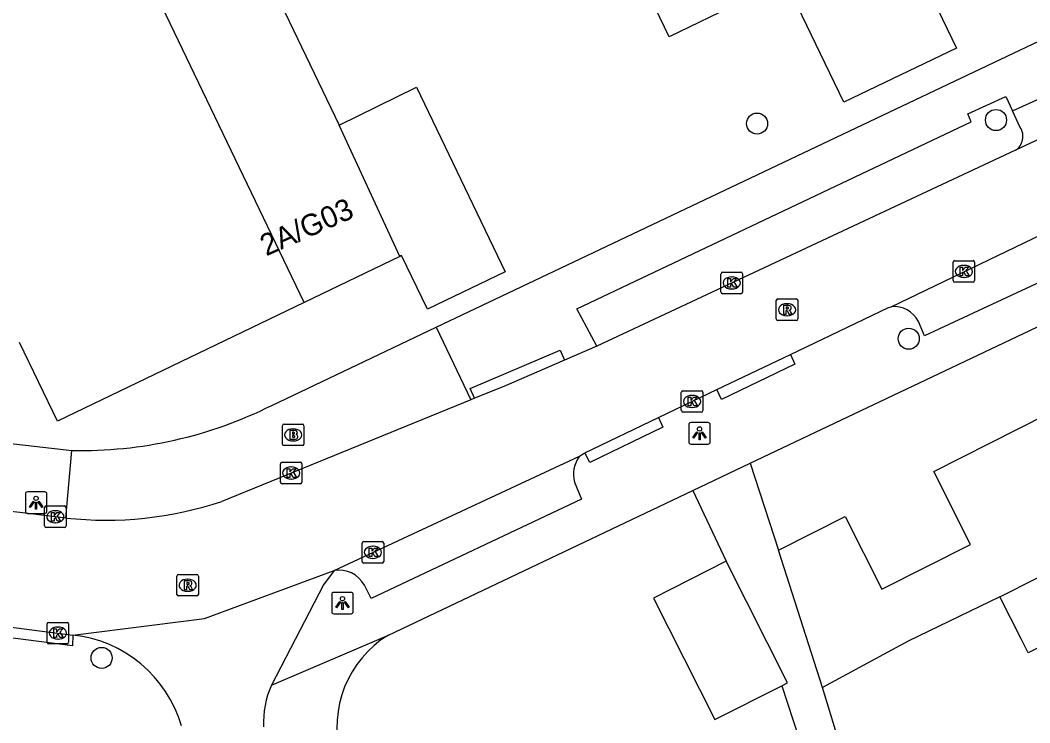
# Model space of a CAD drawing. Extents: x 162250 to 162654, y 380744 to 381605.
# Drawn here: x 162422.34 to 162469.23, y 381351.06 to 381383.66 of the extents above; entities that cross this region are included whole.
import ezdxf

# ---------------------------------------------------------------- set-up
doc = ezdxf.new("R2010")
doc.units = 0
for name, color, linetype in [('IMGEO_Boom', 7, 'Continuous'), ('IMGEO_Brandkraan', 7, 'Continuous'), ('IMGEO_Kolk', 7, 'Continuous'), ('IMGEO_Lichtpunt', 7, 'Continuous'), ('IMGEO_Pand', 7, 'Continuous'), ('IMGEO_Pand_nummerreeks', 7, 'Continuous'), ('IMGEO_Parkeervlak_open', 7, 'Continuous'), ('IMGEO_Rijbaan_lokaal_open', 7, 'Continuous'), ('IMGEO_Rioolput', 7, 'Continuous'), ('IMGEO_Voetpad_open', 7, 'Continuous')]:
    doc.layers.add(name, color=color, linetype=linetype)

msp = doc.modelspace()

# ---------------------------------------------------------------- linework, layer by layer
at = {"layer": 'IMGEO_Boom'}
for centre in [(162456.565, 381378.859), (162467.661, 381379.024), (162463.607, 381368.877), (162426.124, 381354.067)]:
    msp.add_circle(centre, 0.489, dxfattribs=at)
at = {"layer": 'IMGEO_Brandkraan'}
for p, q in [((162434.521, 381363.989), (162434.521, 381364.841)), ((162434.596, 381364.915), (162435.448, 381364.915)), ((162435.522, 381364.841), (162435.522, 381363.989)), ((162435.009, 381364.695), (162435.034, 381364.695)), ((162435.448, 381363.915), (162434.596, 381363.915)), ((162435.032, 381364.135), (162435.007, 381364.135))]:
    msp.add_line(p, q, dxfattribs=at)
for points in [[(162434.521, 381363.989), (162434.521, 381364.841)], [(162434.596, 381364.915), (162435.448, 381364.915)], [(162435.522, 381364.841), (162435.522, 381363.989)], [(162434.869, 381364.615), (162434.869, 381364.215), (162435.082, 381364.215)], [(162435.1, 381364.615), (162434.869, 381364.615)], [(162435.048, 381364.534), (162434.994, 381364.534), (162434.994, 381364.458)], [(162434.994, 381364.458), (162435.047, 381364.458)], [(162435.056, 381364.382), (162434.994, 381364.382), (162434.994, 381364.301)], [(162435.448, 381363.915), (162434.596, 381363.915)], [(162434.994, 381364.301), (162435.056, 381364.301)]]:
    msp.add_lwpolyline(points, dxfattribs=at)
for centre, radius, start, end in [((162434.598, 381364.839), 0.0765, 91.552, 178.448), ((162434.598, 381364.839), 0.0765, 91.552, 178.448), ((162435.446, 381364.839), 0.0765, 1.552, 88.448), ((162435.446, 381364.839), 0.0765, 1.552, 88.448), ((162435.049, 381364.496), 0.0379, 267.8285, 90.9355), ((162435.057, 381364.341), 0.0404, 269.8759, 90.5077), ((162435.104, 381364.47), 0.145, 59.4692, 91.5367), ((162435.129, 381364.517), 0.0922, 285.5137, 58.1501), ((162435.134, 381364.325), 0.105, 301.3115, 78.989), ((162434.598, 381363.991), 0.0765, 181.552, 268.448), ((162434.598, 381363.991), 0.0765, 181.552, 268.448), ((162435.088, 381364.466), 0.251, 268.6676, 293.5347), ((162435.446, 381363.991), 0.0765, 271.552, 358.448), ((162435.446, 381363.991), 0.0765, 271.552, 358.448)]:
    msp.add_arc(centre, radius, start, end, dxfattribs=at)
for centre, major_axis, ratio, start_param, end_param in [((162435.008, 381364.415), (-0.387, 0.002), 0.722429, 4.712389, 7.853982), ((162435.033, 381364.415), (-0.39, 0.002), 0.717154, 1.570796, 4.712389)]:
    msp.add_ellipse(centre, major_axis=major_axis, ratio=ratio, start_param=start_param, end_param=end_param, dxfattribs=at)
at = {"layer": 'IMGEO_Kolk'}
for p, q in [((162465.668, 381371.572), (162465.668, 381372.424)), ((162465.743, 381372.498), (162466.595, 381372.498)), ((162466.669, 381372.424), (162466.669, 381371.572)), ((162454.889, 381371.04), (162454.889, 381371.892)), ((162454.964, 381371.966), (162455.816, 381371.966)), ((162455.89, 381371.892), (162455.89, 381371.04)), ((162466.156, 381372.278), (162466.181, 381372.278)), ((162455.377, 381371.746), (162455.402, 381371.746)), ((162466.595, 381371.498), (162465.743, 381371.498)), ((162466.179, 381371.718), (162466.154, 381371.718)), ((162455.816, 381370.966), (162454.964, 381370.966)), ((162455.4, 381371.186), (162455.375, 381371.186)), ((162453.047, 381365.539), (162453.047, 381366.391)), ((162453.122, 381366.465), (162453.974, 381366.465)), ((162453.535, 381366.245), (162453.56, 381366.245)), ((162454.048, 381366.391), (162454.048, 381365.539)), ((162453.974, 381365.465), (162453.122, 381365.465)), ((162453.558, 381365.685), (162453.533, 381365.685)), ((162434.427, 381362.219), (162434.427, 381363.071)), ((162434.502, 381363.145), (162435.354, 381363.145)), ((162435.428, 381363.071), (162435.428, 381362.219)), ((162434.915, 381362.925), (162434.94, 381362.925)), ((162435.354, 381362.145), (162434.502, 381362.145)), ((162434.938, 381362.365), (162434.913, 381362.365)), ((162423.55, 381361.117), (162424.402, 381361.117)), ((162423.475, 381360.191), (162423.475, 381361.043)), ((162423.963, 381360.897), (162423.988, 381360.897)), ((162424.476, 381361.043), (162424.476, 381360.191)), ((162423.986, 381360.337), (162423.961, 381360.337)), ((162424.402, 381360.117), (162423.55, 381360.117)), ((162438.223, 381358.54), (162438.223, 381359.392)), ((162438.298, 381359.466), (162439.15, 381359.466)), ((162438.711, 381359.246), (162438.736, 381359.246)), ((162439.224, 381359.392), (162439.224, 381358.54)), ((162439.15, 381358.466), (162438.298, 381358.466)), ((162438.734, 381358.686), (162438.709, 381358.686)), ((162423.592, 381354.79), (162423.592, 381355.642)), ((162423.667, 381355.716), (162424.519, 381355.716)), ((162424.08, 381355.496), (162424.105, 381355.496)), ((162424.593, 381355.642), (162424.593, 381354.79)), ((162424.519, 381354.716), (162423.667, 381354.716)), ((162424.103, 381354.936), (162424.078, 381354.936))]:
    msp.add_line(p, q, dxfattribs=at)
for points in [[(162465.668, 381371.572), (162465.668, 381372.424)], [(162465.743, 381372.498), (162466.595, 381372.498)], [(162466.669, 381372.424), (162466.669, 381371.572)], [(162454.889, 381371.04), (162454.889, 381371.892)], [(162454.964, 381371.966), (162455.816, 381371.966)], [(162455.89, 381371.892), (162455.89, 381371.04)], [(162465.989, 381372.198), (162466.112, 381372.198), (162466.112, 381372.047), (162466.242, 381372.198), (162466.406, 381372.198), (162466.26, 381372.047), (162466.413, 381371.798), (162466.261, 381371.798), (162466.176, 381371.962), (162466.112, 381371.895), (162466.112, 381371.798), (162465.989, 381371.798), (162465.989, 381372.198)], [(162455.21, 381371.666), (162455.333, 381371.666), (162455.333, 381371.515), (162455.463, 381371.666), (162455.627, 381371.666), (162455.481, 381371.515), (162455.634, 381371.266), (162455.482, 381371.266), (162455.397, 381371.43), (162455.333, 381371.363), (162455.333, 381371.266), (162455.21, 381371.266), (162455.21, 381371.666)], [(162466.595, 381371.498), (162465.743, 381371.498)], [(162455.816, 381370.966), (162454.964, 381370.966)], [(162453.047, 381365.539), (162453.047, 381366.391)], [(162453.122, 381366.465), (162453.974, 381366.465)], [(162454.048, 381366.391), (162454.048, 381365.539)], [(162453.368, 381366.165), (162453.491, 381366.165), (162453.491, 381366.014), (162453.621, 381366.165), (162453.785, 381366.165), (162453.639, 381366.014), (162453.792, 381365.765), (162453.64, 381365.765), (162453.555, 381365.929), (162453.491, 381365.862), (162453.491, 381365.765), (162453.368, 381365.765), (162453.368, 381366.165)], [(162453.974, 381365.465), (162453.122, 381365.465)], [(162434.427, 381362.219), (162434.427, 381363.071)], [(162434.502, 381363.145), (162435.354, 381363.145)], [(162435.428, 381363.071), (162435.428, 381362.219)], [(162434.748, 381362.845), (162434.871, 381362.845), (162434.871, 381362.694), (162435.001, 381362.845), (162435.165, 381362.845), (162435.019, 381362.694), (162435.172, 381362.445), (162435.02, 381362.445), (162434.935, 381362.609), (162434.871, 381362.542), (162434.871, 381362.445), (162434.748, 381362.445), (162434.748, 381362.845)], [(162435.354, 381362.145), (162434.502, 381362.145)], [(162423.55, 381361.117), (162424.402, 381361.117)], [(162423.475, 381360.191), (162423.475, 381361.043)], [(162423.796, 381360.817), (162423.919, 381360.817), (162423.919, 381360.666), (162424.049, 381360.817), (162424.213, 381360.817), (162424.067, 381360.666), (162424.22, 381360.417), (162424.068, 381360.417), (162423.983, 381360.581), (162423.919, 381360.514), (162423.919, 381360.417), (162423.796, 381360.417), (162423.796, 381360.817)], [(162424.476, 381361.043), (162424.476, 381360.191)], [(162424.402, 381360.117), (162423.55, 381360.117)], [(162438.223, 381358.54), (162438.223, 381359.392)], [(162438.298, 381359.466), (162439.15, 381359.466)], [(162439.224, 381359.392), (162439.224, 381358.54)], [(162438.544, 381359.166), (162438.667, 381359.166), (162438.667, 381359.015), (162438.797, 381359.166), (162438.961, 381359.166), (162438.815, 381359.015), (162438.968, 381358.766), (162438.816, 381358.766), (162438.731, 381358.93), (162438.667, 381358.863), (162438.667, 381358.766), (162438.544, 381358.766), (162438.544, 381359.166)], [(162439.15, 381358.466), (162438.298, 381358.466)], [(162423.592, 381354.79), (162423.592, 381355.642)], [(162423.667, 381355.716), (162424.519, 381355.716)], [(162424.593, 381355.642), (162424.593, 381354.79)], [(162423.913, 381355.416), (162424.036, 381355.416), (162424.036, 381355.265), (162424.166, 381355.416), (162424.33, 381355.416), (162424.184, 381355.265), (162424.337, 381355.016), (162424.185, 381355.016), (162424.1, 381355.18), (162424.036, 381355.113), (162424.036, 381355.016), (162423.913, 381355.016), (162423.913, 381355.416)], [(162424.519, 381354.716), (162423.667, 381354.716)]]:
    msp.add_lwpolyline(points, dxfattribs=at)
for centre, start, end in [((162465.745, 381372.422), 91.552, 178.448), ((162465.745, 381372.422), 91.552, 178.448), ((162466.593, 381372.422), 1.552, 88.448), ((162466.593, 381372.422), 1.552, 88.448), ((162454.966, 381371.89), 91.552, 178.448), ((162454.966, 381371.89), 91.552, 178.448), ((162455.814, 381371.89), 1.552, 88.448), ((162455.814, 381371.89), 1.552, 88.448), ((162465.745, 381371.574), 181.552, 268.448), ((162465.745, 381371.574), 181.552, 268.448), ((162466.593, 381371.574), 271.552, 358.448), ((162466.593, 381371.574), 271.552, 358.448), ((162454.966, 381371.042), 181.552, 268.448), ((162454.966, 381371.042), 181.552, 268.448), ((162455.814, 381371.042), 271.552, 358.448), ((162455.814, 381371.042), 271.552, 358.448), ((162453.124, 381366.389), 91.552, 178.448), ((162453.124, 381366.389), 91.552, 178.448), ((162453.972, 381366.389), 1.552, 88.448), ((162453.972, 381366.389), 1.552, 88.448), ((162453.124, 381365.541), 181.552, 268.448), ((162453.124, 381365.541), 181.552, 268.448), ((162453.972, 381365.541), 271.552, 358.448), ((162453.972, 381365.541), 271.552, 358.448), ((162434.504, 381363.069), 91.552, 178.448), ((162434.504, 381363.069), 91.552, 178.448), ((162435.352, 381363.069), 1.552, 88.448), ((162435.352, 381363.069), 1.552, 88.448), ((162434.504, 381362.221), 181.552, 268.448), ((162434.504, 381362.221), 181.552, 268.448), ((162435.352, 381362.221), 271.552, 358.448), ((162435.352, 381362.221), 271.552, 358.448), ((162423.552, 381361.041), 91.552, 178.448), ((162423.552, 381361.041), 91.552, 178.448), ((162424.4, 381361.041), 1.552, 88.448), ((162424.4, 381361.041), 1.552, 88.448), ((162423.552, 381360.193), 181.552, 268.448), ((162423.552, 381360.193), 181.552, 268.448), ((162424.4, 381360.193), 271.552, 358.448), ((162424.4, 381360.193), 271.552, 358.448), ((162438.3, 381359.39), 91.552, 178.448), ((162438.3, 381359.39), 91.552, 178.448), ((162439.148, 381359.39), 1.552, 88.448), ((162439.148, 381359.39), 1.552, 88.448), ((162438.3, 381358.542), 181.552, 268.448), ((162438.3, 381358.542), 181.552, 268.448), ((162439.148, 381358.542), 271.552, 358.448), ((162439.148, 381358.542), 271.552, 358.448), ((162423.669, 381355.64), 91.552, 178.448), ((162423.669, 381355.64), 91.552, 178.448), ((162424.517, 381355.64), 1.552, 88.448), ((162424.517, 381355.64), 1.552, 88.448), ((162423.669, 381354.792), 181.552, 268.448), ((162423.669, 381354.792), 181.552, 268.448), ((162424.517, 381354.792), 271.552, 358.448), ((162424.517, 381354.792), 271.552, 358.448)]:
    msp.add_arc(centre, 0.0765, start, end, dxfattribs=at)
for centre, major_axis, ratio, start_param, end_param in [((162466.155, 381371.998), (-0.387, 0.002), 0.722429, 4.712389, 7.853982), ((162466.18, 381371.998), (-0.39, 0.002), 0.717154, 1.570796, 4.712389), ((162455.376, 381371.466), (-0.387, 0.002), 0.722429, 4.712389, 7.853982), ((162455.401, 381371.466), (-0.39, 0.002), 0.717154, 1.570796, 4.712389), ((162453.534, 381365.965), (-0.387, 0.002), 0.722429, 4.712389, 7.853982), ((162453.559, 381365.965), (-0.39, 0.002), 0.717154, 1.570796, 4.712389), ((162434.914, 381362.645), (-0.387, 0.002), 0.722429, 4.712389, 7.853982), ((162434.939, 381362.645), (-0.39, 0.002), 0.717154, 1.570796, 4.712389), ((162423.962, 381360.617), (-0.387, 0.002), 0.722429, 4.712389, 7.853982), ((162423.987, 381360.617), (-0.39, 0.002), 0.717154, 1.570796, 4.712389), ((162438.71, 381358.966), (-0.387, 0.002), 0.722429, 4.712389, 7.853982), ((162438.735, 381358.966), (-0.39, 0.002), 0.717154, 1.570796, 4.712389), ((162424.079, 381355.216), (-0.387, 0.002), 0.722429, 4.712389, 7.853982), ((162424.104, 381355.216), (-0.39, 0.002), 0.717154, 1.570796, 4.712389)]:
    msp.add_ellipse(centre, major_axis=major_axis, ratio=ratio, start_param=start_param, end_param=end_param, dxfattribs=at)
at = {"layer": 'IMGEO_Lichtpunt'}
for p, q in [((162453.392, 381364.892), (162453.392, 381364.085)), ((162453.392, 381364.892), (162453.392, 381364.085)), ((162454.294, 381364.987), (162453.486, 381364.987)), ((162454.294, 381364.987), (162453.486, 381364.987)), ((162454.388, 381364.085), (162454.388, 381364.892)), ((162454.388, 381364.085), (162454.388, 381364.892)), ((162453.486, 381363.991), (162454.294, 381363.991)), ((162453.486, 381363.991), (162454.294, 381363.991)), ((162422.584, 381361.672), (162422.584, 381360.865)), ((162422.584, 381361.672), (162422.584, 381360.865)), ((162423.486, 381361.767), (162422.678, 381361.767)), ((162423.486, 381361.767), (162422.678, 381361.767)), ((162423.58, 381360.865), (162423.58, 381361.672)), ((162423.58, 381360.865), (162423.58, 381361.672)), ((162422.678, 381360.771), (162423.486, 381360.771)), ((162422.678, 381360.771), (162423.486, 381360.771)), ((162436.812, 381357.014), (162436.812, 381356.207)), ((162436.812, 381357.014), (162436.812, 381356.207)), ((162437.714, 381357.109), (162436.906, 381357.109)), ((162437.714, 381357.109), (162436.906, 381357.109)), ((162437.808, 381356.207), (162437.808, 381357.014)), ((162437.808, 381356.207), (162437.808, 381357.014)), ((162436.906, 381356.113), (162437.714, 381356.113)), ((162436.906, 381356.113), (162437.714, 381356.113))]:
    msp.add_line(p, q, dxfattribs=at)
for points in [[(162453.766, 381364.556), (162453.805, 381364.528), (162453.617, 381364.266), (162453.579, 381364.293), (162453.766, 381364.556)], [(162453.868, 381364.508), (162453.915, 381364.508), (162453.915, 381364.186), (162453.868, 381364.186), (162453.868, 381364.508)], [(162453.978, 381364.528), (162454.016, 381364.555), (162454.203, 381364.293), (162454.164, 381364.265), (162453.978, 381364.528)], [(162422.958, 381361.336), (162422.997, 381361.308), (162422.809, 381361.046), (162422.771, 381361.073), (162422.958, 381361.336)], [(162423.06, 381361.288), (162423.107, 381361.288), (162423.107, 381360.966), (162423.06, 381360.966), (162423.06, 381361.288)], [(162423.17, 381361.308), (162423.208, 381361.335), (162423.395, 381361.073), (162423.356, 381361.045), (162423.17, 381361.308)], [(162437.186, 381356.678), (162437.225, 381356.65), (162437.037, 381356.388), (162436.999, 381356.415), (162437.186, 381356.678)], [(162437.288, 381356.63), (162437.335, 381356.63), (162437.335, 381356.308), (162437.288, 381356.308), (162437.288, 381356.63)], [(162437.398, 381356.65), (162437.436, 381356.677), (162437.623, 381356.415), (162437.584, 381356.387), (162437.398, 381356.65)]]:
    msp.add_lwpolyline(points, dxfattribs=at)
for centre in [(162453.891, 381364.69), (162423.083, 381361.47), (162437.311, 381356.812)]:
    msp.add_circle(centre, 0.0994, dxfattribs=at)
for centre, start, end in [((162453.486, 381364.892), 90, 180), ((162453.486, 381364.892), 90, 180), ((162454.294, 381364.892), 0, 90), ((162454.294, 381364.892), 0, 90), ((162453.486, 381364.085), 180, 270), ((162453.486, 381364.085), 180, 270), ((162454.294, 381364.085), 270, 0), ((162454.294, 381364.085), 270, 360), ((162422.678, 381361.672), 90, 180), ((162422.678, 381361.672), 90, 180), ((162423.486, 381361.672), 0, 90), ((162423.486, 381361.672), 0, 90), ((162422.678, 381360.865), 180, 270), ((162422.678, 381360.865), 180, 270), ((162423.486, 381360.865), 270, 0), ((162423.486, 381360.865), 270, 360), ((162436.906, 381357.014), 90, 180), ((162436.906, 381357.014), 90, 180), ((162437.714, 381357.014), 0, 90), ((162437.714, 381357.014), 0, 90), ((162436.906, 381356.207), 180, 270), ((162436.906, 381356.207), 180, 270), ((162437.714, 381356.207), 270, 0), ((162437.714, 381356.207), 270, 360)]:
    msp.add_arc(centre, 0.0946, start, end, dxfattribs=at)
at = {"layer": 'IMGEO_Pand'}
for points in [[(162466.136, 381393.238), (162469.023, 381387.226), (162464.525, 381385.066), (162465.824, 381382.361), (162460.595, 381379.851), (162457.799, 381385.674), (162455.662, 381384.648), (162455.753, 381384.459), (162452.481, 381382.887), (162451.185, 381385.586)], [(162435.524, 381370.559), (162428.932, 381384.283), (162433.466, 381386.461)], [(162433.466, 381386.461), (162437.151, 381378.79)], [(162437.151, 381378.79), (162440.742, 381380.542), (162444.86, 381371.981), (162441.254, 381370.249), (162440.059, 381372.737), (162439.968, 381372.693)], [(162439.968, 381372.693), (162437.151, 381378.79)], [(162439.968, 381372.693), (162435.524, 381370.559)], [(162435.524, 381370.559), (162424.069, 381365.057), (162422.315, 381368.705)], [(162457.556, 381359.063), (162460.657, 381360.629), (162462.362, 381357.254), (162466.481, 381359.333), (162464.771, 381362.72), (162468.684, 381364.696), (162476.895, 381368.842), (162479.86, 381362.97)], [(162467.843, 381356.9), (162479.86, 381362.97)], [(162459.604, 381352.686), (162457.556, 381359.063)], [(162455.135, 381358.552), (162451.752, 381356.844), (162454.599, 381351.205), (162457.711, 381352.776)], [(162457.711, 381352.776), (162457.982, 381352.913), (162455.135, 381358.552)], [(162467.843, 381356.9), (162463.58, 381354.841), (162459.604, 381352.686)], [(162475.416, 381350.806), (162474.176, 381353.793), (162472.949, 381356.225), (162469.152, 381354.307), (162468.841, 381354.924), (162467.843, 381356.9)]]:
    msp.add_lwpolyline(points, dxfattribs=at)
at = {"layer": 'IMGEO_Parkeervlak_open'}
for points in [[(162468.788, 381378.68), (162468.42, 381379.455)], [(162434.029, 381365.783), (162441.657, 381369.405)]]:
    msp.add_lwpolyline(points, dxfattribs=at)
for centre, radius, start, end in [((162468.149, 381378.26), 0.765, 302.9846, 33.2762), ((162425.178, 381383.446), 19.756, 268.7395, 296.6171)]:
    msp.add_arc(centre, radius, start, end, dxfattribs=at)
at = {"layer": 'IMGEO_Rijbaan_lokaal_open'}
for points in [[(162476.356, 381381.26), (162468.565, 381377.619)], [(162468.565, 381377.619), (162449.12, 381368.536)], [(162462.791, 381370.36), (162474.309, 381375.894)], [(162458.111, 381368.146), (162462.675, 381370.322), (162462.791, 381370.36)], [(162449.12, 381368.536), (162447.618, 381367.886)], [(162454.698, 381366.515), (162458.111, 381368.146)], [(162447.618, 381367.886), (162444.8, 381366.666), (162443.437, 381366.111)], [(162451.983, 381365.217), (162454.698, 381366.515)], [(162443.272, 381366.044), (162431.702, 381361.33)], [(162443.437, 381366.111), (162443.272, 381366.044)], [(162448.565, 381363.584), (162451.983, 381365.217)], [(162436.919, 381358.12), (162448.317, 381363.42)], [(162448.317, 381363.42), (162448.411, 381363.482), (162448.565, 381363.584)], [(162424.469, 381360.557), (162422.583, 381360.789), (162418.002, 381361.308), (162417.694, 381361.338)], [(162424.79, 381355.126), (162430.909, 381355.898), (162436.919, 381358.12)], [(162436.919, 381358.12), (162436.427, 381357.46), (162434.009, 381352.807)], [(162419.535, 381355.796), (162424.79, 381355.126)]]:
    msp.add_lwpolyline(points, dxfattribs=at)
for centre, radius, start, end in [((162426.321, 381377.453), 16.997, 263.7444, 288.4559), ((162424.169, 381349.266), 5.893, 16.1727, 83.9504), ((162437.865, 381351.085), 4.222, 155.9379, 183.0328)]:
    msp.add_arc(centre, radius, start, end, dxfattribs=at)
at = {"layer": 'IMGEO_Rioolput'}
for p, q in [((162457.457, 381369.795), (162457.457, 381370.647)), ((162457.532, 381370.721), (162458.384, 381370.721)), ((162457.945, 381370.501), (162457.97, 381370.501)), ((162458.458, 381370.647), (162458.458, 381369.795)), ((162458.384, 381369.721), (162457.532, 381369.721)), ((162457.968, 381369.941), (162457.943, 381369.941)), ((162429.621, 381357.014), (162429.621, 381357.866)), ((162429.696, 381357.94), (162430.548, 381357.94)), ((162430.622, 381357.866), (162430.622, 381357.014)), ((162430.109, 381357.72), (162430.134, 381357.72)), ((162430.548, 381356.94), (162429.696, 381356.94)), ((162430.132, 381357.16), (162430.107, 381357.16))]:
    msp.add_line(p, q, dxfattribs=at)
for points in [[(162457.457, 381369.795), (162457.457, 381370.647)], [(162457.532, 381370.721), (162458.384, 381370.721)], [(162458.458, 381370.647), (162458.458, 381369.795)], [(162458.046, 381370.419), (162457.794, 381370.421), (162457.794, 381370.021)], [(162457.794, 381370.021), (162457.918, 381370.021), (162457.918, 381370.183), (162457.929, 381370.183)], [(162457.972, 381370.34), (162457.918, 381370.34), (162457.918, 381370.259)], [(162457.918, 381370.259), (162457.97, 381370.259)], [(162457.976, 381370.154), (162458.047, 381370.021), (162458.187, 381370.021), (162458.122, 381370.147)], [(162458.384, 381369.721), (162457.532, 381369.721)], [(162429.621, 381357.014), (162429.621, 381357.866)], [(162429.696, 381357.94), (162430.548, 381357.94)], [(162430.622, 381357.866), (162430.622, 381357.014)], [(162430.21, 381357.638), (162429.958, 381357.64), (162429.958, 381357.24)], [(162429.958, 381357.24), (162430.082, 381357.24), (162430.082, 381357.402), (162430.093, 381357.402)], [(162430.136, 381357.559), (162430.082, 381357.559), (162430.082, 381357.478)], [(162430.082, 381357.478), (162430.134, 381357.478)], [(162430.14, 381357.373), (162430.211, 381357.24), (162430.351, 381357.24), (162430.286, 381357.366)], [(162430.548, 381356.94), (162429.696, 381356.94)]]:
    msp.add_lwpolyline(points, dxfattribs=at)
for centre, radius, start, end in [((162457.534, 381370.645), 0.0765, 91.552, 178.448), ((162457.534, 381370.645), 0.0765, 91.552, 178.448), ((162458.382, 381370.645), 0.0765, 1.552, 88.448), ((162458.382, 381370.645), 0.0765, 1.552, 88.448), ((162457.928, 381370.13), 0.0533, 26.0293, 88.6989), ((162457.954, 381370.448), 0.19, 274.7715, 282.9687), ((162457.978, 381370.244), 0.0964, 77.0061, 93.1865), ((162457.992, 381370.301), 0.0378, 276.6634, 79.6772), ((162458.045, 381370.309), 0.109, 350.3612, 89.416), ((162458.043, 381370.309), 0.112, 277.5842, 350.9817), ((162458.027, 381370.094), 0.108, 29.5134, 73.7905), ((162457.534, 381369.797), 0.0765, 181.552, 268.448), ((162457.534, 381369.797), 0.0765, 181.552, 268.448), ((162458.382, 381369.797), 0.0765, 271.552, 358.448), ((162458.382, 381369.797), 0.0765, 271.552, 358.448), ((162429.698, 381357.864), 0.0765, 91.552, 178.448), ((162429.698, 381357.864), 0.0765, 91.552, 178.448), ((162430.546, 381357.864), 0.0765, 1.552, 88.448), ((162430.546, 381357.864), 0.0765, 1.552, 88.448), ((162430.092, 381357.349), 0.0533, 26.0293, 88.6989), ((162430.118, 381357.667), 0.19, 274.7715, 282.9687), ((162430.142, 381357.463), 0.0964, 77.0061, 93.1865), ((162430.156, 381357.52), 0.0378, 276.6634, 79.6772), ((162430.209, 381357.528), 0.109, 350.3612, 89.416), ((162430.207, 381357.528), 0.112, 277.5842, 350.9817), ((162430.191, 381357.313), 0.108, 29.5134, 73.7905), ((162429.698, 381357.016), 0.0765, 181.552, 268.448), ((162429.698, 381357.016), 0.0765, 181.552, 268.448), ((162430.546, 381357.016), 0.0765, 271.552, 358.448), ((162430.546, 381357.016), 0.0765, 271.552, 358.448)]:
    msp.add_arc(centre, radius, start, end, dxfattribs=at)
for centre, major_axis, ratio, start_param, end_param in [((162457.944, 381370.221), (-0.387, 0.002), 0.722429, 4.712389, 7.853982), ((162457.969, 381370.221), (-0.39, 0.002), 0.717154, 1.570796, 4.712389), ((162430.108, 381357.44), (-0.387, 0.002), 0.722429, 4.712389, 7.853982), ((162430.133, 381357.44), (-0.39, 0.002), 0.717154, 1.570796, 4.712389)]:
    msp.add_ellipse(centre, major_axis=major_axis, ratio=ratio, start_param=start_param, end_param=end_param, dxfattribs=at)
at = {"layer": 'IMGEO_Voetpad_open'}
for points in [[(162441.657, 381369.405), (162474.869, 381385.175)], [(162468.42, 381379.455), (162474.81, 381382.32), (162474.966, 381381.839)], [(162449.12, 381368.536), (162448.188, 381370.267), (162466.507, 381378.933), (162466.352, 381379.313), (162468.113, 381380.119), (162468.42, 381379.455)], [(162331.101, 381374.491), (162340.622, 381373.413), (162412.338, 381365.108), (162424.743, 381363.694)], [(162456.249, 381363.099), (162480.129, 381374.422)], [(162473.927, 381374.467), (162474.25, 381373.619), (162464.344, 381369.014), (162464.06, 381369.672)], [(162441.657, 381369.405), (162443.272, 381366.044)], [(162443.437, 381366.111), (162443.246, 381366.573), (162447.427, 381368.348), (162447.618, 381367.886)], [(162458.111, 381368.146), (162458.323, 381367.694), (162454.91, 381366.063), (162454.698, 381366.515)], [(162451.983, 381365.217), (162452.195, 381364.765), (162448.793, 381363.14), (162448.565, 381363.584)], [(162424.469, 381360.557), (162424.743, 381363.694)], [(162453.579, 381361.833), (162456.249, 381363.099)], [(162456.249, 381363.099), (162457.556, 381359.063)], [(162448.08, 381362.217), (162448.403, 381361.432), (162438.636, 381356.828), (162438.327, 381357.435)], [(162439.44, 381355.128), (162453.579, 381361.833)], [(162453.579, 381361.833), (162455.135, 381358.552)], [(162424.79, 381355.126), (162424.767, 381354.626), (162419.468, 381355.301), (162419.535, 381355.796)], [(162434.009, 381352.807), (162439.44, 381355.128)], [(162457.711, 381352.776), (162458.766, 381349.552)], [(162467.968, 381325.289), (162459.604, 381352.686)]]:
    msp.add_lwpolyline(points, dxfattribs=at)
for centre, radius, start, end in [((162462.918, 381369.081), 1.286, 27.3832, 95.6874), ((162449.435, 381362.575), 1.401, 142.9141, 194.796), ((162437.156, 381356.817), 1.324, 27.8065, 100.3072), ((162442.062, 381350.86), 5.009, 121.5586, 194.8991)]:
    msp.add_arc(centre, radius, start, end, dxfattribs=at)

# ---------------------------------------------------------------- texts
at = {"layer": 'IMGEO_Pand_nummerreeks'}
msp.add_text('2A/G03', height=1, rotation=23.8387, dxfattribs=at).set_placement((162433.768, 381372.695))

doc.saveas('drawing.dxf')
